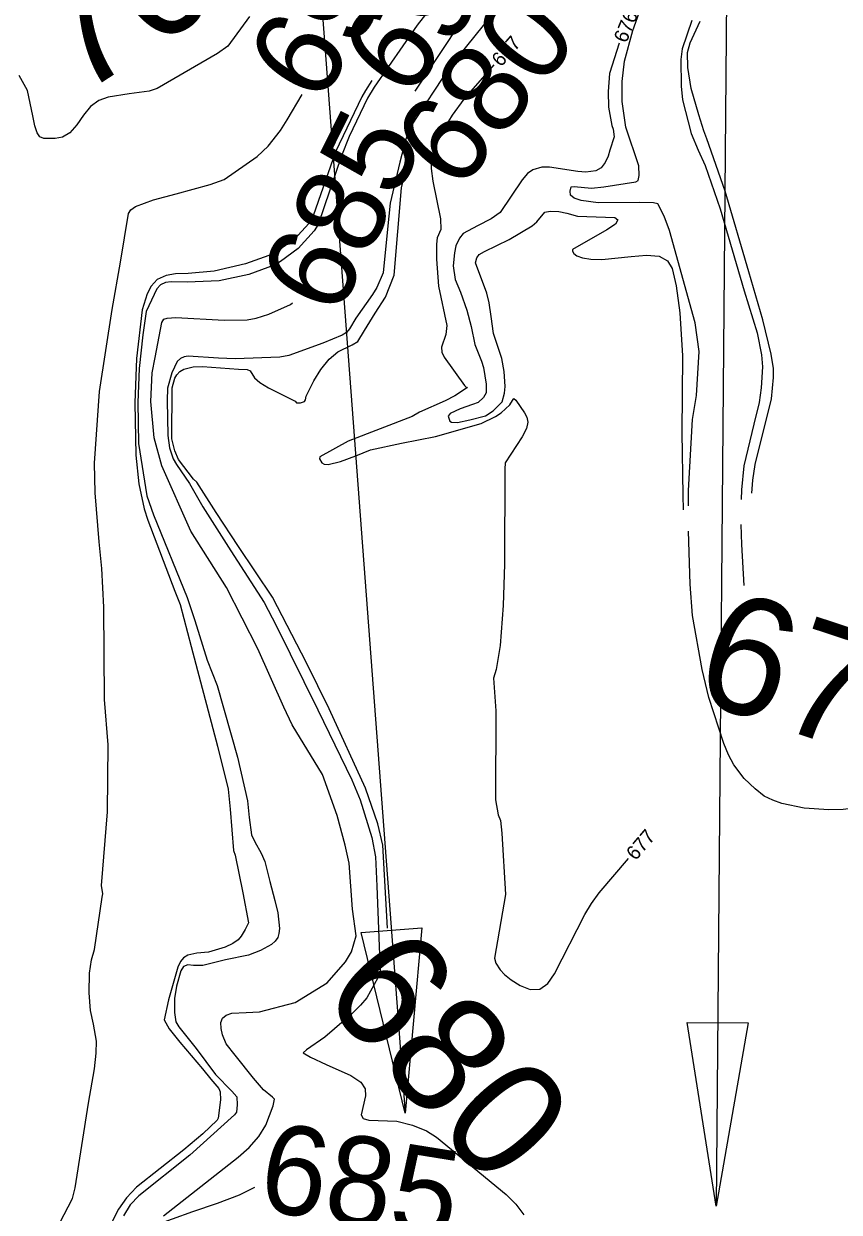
# Model space of a CAD drawing. Extents: x -291892836 to 2945206, y -477993085 to 1832792.
# Drawn here: x 1851264 to 1851493.5, y 544449.7 to 544783.9 of the extents above; entities that cross this region are included whole.
import ezdxf

# ---------------------------------------------------------------- set-up
doc = ezdxf.new("R2010")
doc.units = 0
for name, color, linetype in [('DT_X_Contour_Minor', 7, 'Continuous'), ('DT_X_Terrain_Ground_Line', 7, 'Continuous'), ('Level 19', 7, 'Continuous'), ('Level 40', 7, 'Continuous')]:
    doc.layers.add(name, color=color, linetype=linetype)

msp = doc.modelspace()

# ---------------------------------------------------------------- linework, layer by layer
at = {"layer": 'DT_X_Contour_Minor'}
for points in [[(1851388.6, 544801.3), (1851374.75, 544783.55), (1851362.59, 544766.11), (1851360.76, 544762.96), (1851355.57, 544752.19), (1851353.43, 544746.73), (1851346.86, 544727.5), (1851345.74, 544725.66), (1851341.27, 544720.75), (1851336.31, 544717.04)], [(1851402.99, 544796.19), (1851393.33, 544783.45), (1851383.94, 544771.77), (1851372.99, 544755.12), (1851371.54, 544751.49), (1851369.83, 544745.01), (1851367.12, 544733.48), (1851366.34, 544726.15), (1851365.2, 544713.86), (1851363.42, 544709.74), (1851362.19, 544707.78), (1851357.48, 544701.12), (1851355.66, 544698.13), (1851354.83, 544697.14), (1851353.64, 544696.34), (1851348.15, 544694.06), (1851338.66, 544690.65)], [(1851394.08, 544795.1), (1851374.06, 544764.99)], [(1851451.07, 544648.37), (1851451.11, 544652.67), (1851452.24, 544672.6), (1851453.38, 544679.39), (1851454.06, 544691.78), (1851452.97, 544699.83), (1851445.75, 544725.78), (1851444.28, 544729.78), (1851442.48, 544733.27), (1851441.25, 544733.58), (1851437.35, 544733.68), (1851425.67, 544733.57), (1851420.9, 544734.19), (1851418.96, 544734.83), (1851417.89, 544735.68), (1851417.77, 544736.82), (1851418.08, 544738.01), (1851418.9, 544738.14), (1851423.84, 544737.72), (1851427.24, 544738.06), (1851436.24, 544739.47), (1851436.97, 544739.88), (1851437.17, 544741.23), (1851437.12, 544743.97), (1851433.47, 544754.79), (1851432.4, 544762.06), (1851432.4, 544767.69), (1851433.13, 544773.41), (1851435.43, 544782.03), (1851437.64, 544788.29)], [(1851327.59, 544785.92), (1851321.44, 544777.58), (1851318.55, 544775.53), (1851301.57, 544765.7), (1851299.34, 544765), (1851293.65, 544764.18), (1851287.77, 544763.28), (1851285.17, 544762.32), (1851282.85, 544760.66), (1851280.82, 544758.2), (1851278.94, 544755.49), (1851277.02, 544753.26), (1851274.96, 544752.03), (1851272.9, 544751.61), (1851269.64, 544751.68), (1851268.56, 544752.11), (1851267.76, 544753.22), (1851267.15, 544755.2), (1851266.58, 544758)], [(1851452.02, 544784.79), (1851449.33, 544776.86), (1851448.91, 544773.86), (1851449, 544766.37), (1851449.42, 544762.48), (1851451.84, 544753.02), (1851453.8, 544748.35), (1851455.79, 544744.04), (1851460.03, 544731.91), (1851466.72, 544708.85), (1851470.43, 544696.98), (1851471.65, 544690.83), (1851471.89, 544687.41), (1851471.57, 544681.58), (1851470.94, 544677.43), (1851469.52, 544671.28), (1851466.7, 544659.62), (1851465.99, 544652.89), (1851465.91, 544650.13)], [(1851468.91, 544651.96), (1851469.16, 544655.53), (1851469.83, 544660.01), (1851474.43, 544678.47), (1851474.97, 544684.45), (1851475, 544687), (1851474.32, 544690.97), (1851472.02, 544700.66), (1851468.03, 544714.12), (1851461.39, 544736.84), (1851456.23, 544751.51), (1851455.44, 544753.76), (1851454.02, 544758.33), (1851451.83, 544765.72), (1851450.9, 544771.59), (1851450.83, 544775.83), (1851451.59, 544778.51), (1851454.36, 544784.64)], [(1851431.57, 544778.41), (1851428.9, 544769.95), (1851428.45, 544764.83), (1851428.56, 544760.48), (1851429.53, 544755.26), (1851429.86, 544754.26), (1851430.16, 544752.1), (1851428.95, 544748.36), (1851428.46, 544746.7), (1851427.65, 544744.88), (1851426.49, 544743.39), (1851425.01, 544742.56), (1851422.17, 544742.21), (1851419.96, 544742.38), (1851411.93, 544743.56), (1851409.84, 544743.55), (1851407.28, 544742.88), (1851405.75, 544741.84), (1851404.32, 544740.06), (1851398.08, 544730.85), (1851395.56, 544729.1), (1851391.75, 544727.09), (1851387.65, 544724.89), (1851386.68, 544723.58), (1851385.61, 544721.47), (1851385.22, 544719.53), (1851384.88, 544715.87), (1851385.45, 544712.02), (1851386.89, 544708.47), (1851388.67, 544703.35), (1851389.9, 544698.79), (1851390.94, 544693.68), (1851392.8, 544689), (1851393.42, 544687.28), (1851394.16, 544682.6), (1851394.12, 544680.11), (1851393.42, 544678.82), (1851391.86, 544677.42), (1851390.3, 544676.88), (1851386.87, 544675.65), (1851383.99, 544674.35), (1851383.46, 544673.53), (1851383.94, 544672.17), (1851384.42, 544671.86), (1851386.09, 544671.81), (1851389.55, 544672.54), (1851393.93, 544673.69), (1851396.11, 544675.05), (1851398.7, 544677.63), (1851399.31, 544680.02), (1851399.46, 544681.9), (1851399.23, 544686.17), (1851398.56, 544689.79), (1851396.2, 544696.78), (1851395.56, 544701.61), (1851395, 544705.42), (1851394.32, 544708.12), (1851391.12, 544716.65), (1851391.5, 544718.11), (1851392.15, 544718.99), (1851393.65, 544719.86), (1851400.64, 544723.25), (1851407.07, 544727.13), (1851408.43, 544728.2), (1851410.69, 544730.95), (1851412.12, 544731.25), (1851414.63, 544731.1), (1851416.9, 544730.63), (1851419.84, 544729.76), (1851430.35, 544729.47), (1851431.21, 544728.77), (1851430.56, 544727.6), (1851428.15, 544725.94), (1851418.42, 544720.42), (1851418.43, 544719.97), (1851418.81, 544719.34), (1851419.69, 544718.65), (1851421.25, 544718.06), (1851423.61, 544717.7), (1851426.73, 544717.65), (1851434.95, 544718.48), (1851439.28, 544718.88), (1851442.86, 544718.58), (1851445.19, 544717.22), (1851446.49, 544715.09), (1851447.63, 544710.24), (1851448.61, 544702.67), (1851449.36, 544690.54), (1851449.23, 544669.02), (1851449.51, 544651.38), (1851449.62, 544647.19)], [(1851396.33, 544772.33), (1851387.85, 544762.67), (1851384.55, 544758.16), (1851381.51, 544753.18), (1851380.08, 544750.38), (1851378.69, 544744.39), (1851378.65, 544743.25), (1851379.18, 544739.65), (1851381.32, 544729.1), (1851381.38, 544726.07), (1851380.37, 544723.75), (1851380.14, 544721.92), (1851380.19, 544717.76), (1851380.73, 544710.09), (1851383.07, 544699.1), (1851382.76, 544696.52), (1851381.63, 544692.93), (1851381.71, 544691.54), (1851382.35, 544690.15), (1851388.09, 544682.2), (1851388.54, 544681.76), (1851388.88, 544681.6), (1851385.36, 544679.31), (1851382.64, 544677.9), (1851375.43, 544674.65), (1851373.33, 544673.43), (1851355.35, 544666.55), (1851347.3, 544662.14), (1851347.24, 544661.59), (1851347.87, 544660.43), (1851348.61, 544660.03), (1851349.72, 544660), (1851353.13, 544660.83), (1851357.5, 544662.46), (1851361.63, 544664.06), (1851370.32, 544666), (1851379.87, 544667.87), (1851392.72, 544671.46), (1851396.8, 544673.44), (1851398.35, 544674.46), (1851400.82, 544676.71), (1851401.6, 544677.94), (1851401.92, 544678.58), (1851402.46, 544678.08), (1851404.91, 544674.47), (1851405.57, 544673.27), (1851405.89, 544671.86), (1851405.54, 544670.06), (1851404.33, 544667.8), (1851399.5, 544660.49), (1851399.38, 544658.64), (1851399.28, 544632), (1851398.93, 544620.31), (1851398.07, 544609.07), (1851396.95, 544602.38), (1851396.26, 544599.92), (1851396.89, 544590.68), (1851396.81, 544565.7), (1851397.56, 544561.43), (1851398.17, 544559.87), (1851398.52, 544556.33), (1851399.61, 544539.08), (1851396.47, 544521.18), (1851396.85, 544519.79), (1851398.05, 544517.93), (1851399.3, 544516.58), (1851401.16, 544515.03), (1851403.7, 544513.46), (1851406.56, 544512.39), (1851409.28, 544512.43), (1851411.53, 544514), (1851413.38, 544516.72), (1851421.91, 544533.41), (1851423.83, 544536.57), (1851425.92, 544539.51), (1851434.21, 544549.16)], [(1851266.58, 544758), (1851265.11, 544765.12), (1851262.7, 544769.39)], [(1851362.02, 544767.93), (1851360.21, 544765.16), (1851359.2, 544763.39), (1851351.76, 544747.87), (1851345.5, 544729.93), (1851344.37, 544727.82), (1851340.09, 544723.25), (1851334.34, 544719.2), (1851326.45, 544716.38), (1851317.65, 544714.34), (1851310.29, 544713.73), (1851306.76, 544713.58), (1851304.08, 544713.13), (1851301.61, 544712.02), (1851299.85, 544710.13), (1851298.76, 544707.92), (1851297.35, 544703.45), (1851295.79, 544689.74), (1851295.25, 544677.35), (1851295.52, 544662.63), (1851296.39, 544654.57), (1851297.92, 544647.48), (1851298.95, 544644.36), (1851306.58, 544624.4), (1851308.01, 544620.58), (1851311.15, 544608.83), (1851318.59, 544580.77), (1851321.57, 544568.66), (1851322.1, 544563.04), (1851323.08, 544551.45), (1851323.53, 544550.12), (1851325.71, 544539.52), (1851327.25, 544531.12), (1851326.29, 544529.21), (1851325.21, 544527.32), (1851324.36, 544526.29), (1851322.9, 544525.27), (1851320.71, 544524.29), (1851316.05, 544522.9), (1851312.74, 544522.57), (1851310.21, 544521.99), (1851309, 544521.3), (1851308.1, 544520.25), (1851307.37, 544518.62), (1851304.77, 544509.46), (1851303.53, 544503.86), (1851304.91, 544501.34), (1851307.97, 544497.51), (1851314.32, 544490.07), (1851316.66, 544487.15), (1851318.94, 544484.48), (1851319.32, 544483.56), (1851319.37, 544481.31), (1851318.77, 544476.14), (1851318.47, 544475.62), (1851314.41, 544471.76), (1851309.06, 544467.31), (1851295.73, 544456.76), (1851292.9, 544453.75), (1851290.66, 544450.57), (1851288.44, 544446.23)], [(1851274.17, 544446.71), (1851277.72, 544453.59), (1851278.45, 544456.58), (1851282.27, 544480.36), (1851283.95, 544490.04), (1851284.44, 544494.43), (1851284.45, 544497.85), (1851283.64, 544502.58), (1851282.81, 544506.47), (1851282.41, 544511.44), (1851282.55, 544516.96), (1851283.13, 544520.67), (1851283.94, 544523.63), (1851286.05, 544538.32), (1851286.31, 544539.26), (1851285.91, 544541.56), (1851287.57, 544562.36), (1851287.73, 544581.12), (1851286.79, 544593.86), (1851286.57, 544619.82), (1851286.03, 544630.7), (1851285.23, 544638.21), (1851284.14, 544651.97), (1851283.89, 544660.32), (1851285.32, 544680.46), (1851288.9, 544703.59), (1851291.27, 544716.85), (1851293.54, 544730.56), (1851294.16, 544731.61), (1851295.51, 544732.51), (1851300.5, 544734.37), (1851306.94, 544736.06), (1851316.51, 544738.75), (1851320.4, 544740.15), (1851329.67, 544746.56), (1851332.79, 544749.48), (1851336.31, 544753.86), (1851338.17, 544756.85), (1851342.41, 544764.01)], [(1851366.38, 544529.63), (1851365.04, 544552.91), (1851363.68, 544558.94), (1851360.18, 544568.99), (1851349.94, 544591.3), (1851343.59, 544604.19), (1851334.04, 544622.7), (1851324.48, 544636.9), (1851318.17, 544646.45), (1851312.69, 544655.01), (1851311.75, 544655.82), (1851307.61, 544661.4), (1851306.5, 544663.79), (1851305.71, 544667.17), (1851305.77, 544681.53), (1851306.56, 544684.21), (1851307.08, 544685.23), (1851307.9, 544686.11), (1851309.06, 544686.77), (1851311.71, 544687.45), (1851314.35, 544687.52), (1851324.43, 544686.82), (1851326.94, 544686.7), (1851327.75, 544686.28), (1851328.99, 544684.35), (1851330.43, 544683), (1851332.94, 544681.53), (1851340.39, 544677.83), (1851340.74, 544677.34), (1851341.89, 544677.35), (1851343.01, 544677.68), (1851343.29, 544678.12), (1851343.53, 544679.22), (1851345.68, 544683.55), (1851347.65, 544686.72), (1851349.97, 544689.61), (1851352.41, 544691.66), (1851356.41, 544693.66), (1851358.03, 544694.55), (1851359.88, 544697.61), (1851362.92, 544702.56), (1851365.85, 544707.01), (1851368.22, 544713.17), (1851370.36, 544737.8), (1851372.1, 544744.98)], [(1851336.31, 544717.04), (1851334.46, 544716.04), (1851327.39, 544713.39), (1851319.03, 544711.65), (1851310.03, 544711.26), (1851305.51, 544711.36), (1851303.9, 544711.11), (1851302.49, 544710.49), (1851301.49, 544709.4), (1851298.44, 544703.04), (1851297.56, 544696.43), (1851296.54, 544687), (1851296.16, 544677.43), (1851296.35, 544665.86), (1851298.67, 544651.16), (1851300.52, 544645.85), (1851309.99, 544622.59), (1851312.17, 544616.11), (1851315.62, 544604.92), (1851318.48, 544597.79), (1851324.16, 544577.69), (1851326.97, 544565.45), (1851327.43, 544560.75), (1851328.08, 544555.89), (1851329.08, 544553.88), (1851330.87, 544550.67), (1851331.82, 544548.36), (1851333.29, 544542.77), (1851334.71, 544537.38), (1851335.57, 544533.95), (1851335.97, 544529.52), (1851335.84, 544528.13), (1851335.49, 544526.96), (1851334.82, 544525.95), (1851333.74, 544525.03), (1851330.6, 544523.33), (1851327.27, 544522.05), (1851320.82, 544520.73), (1851314.43, 544519.13), (1851311.83, 544519.13), (1851310.19, 544519.26), (1851308.94, 544518.8), (1851308.21, 544517.59), (1851307.03, 544513.25), (1851306.47, 544509.86), (1851306.42, 544505.89), (1851306.86, 544503.22), (1851307.71, 544501.84), (1851312.53, 544495.77), (1851318.01, 544488.43), (1851322.58, 544483.75), (1851323.99, 544482.18), (1851324.1, 544479.91), (1851323.86, 544477.85), (1851323.31, 544477.11), (1851310.75, 544465.78), (1851296.36, 544454.37), (1851293.98, 544451.79), (1851292.05, 544448.71)], [(1851303.32, 544448.67), (1851324.34, 544465.2), (1851327.41, 544467.9), (1851330.18, 544470.98), (1851332.18, 544474.24), (1851334.17, 544479.61), (1851334.59, 544481.53), (1851333.98, 544482.09), (1851331.51, 544484.11), (1851328.68, 544487.4), (1851323.5, 544493.87), (1851321.01, 544497.06), (1851319.99, 544499.58), (1851319.57, 544501.37), (1851319.49, 544503.06), (1851319.96, 544504.33), (1851320.99, 544505.18), (1851322.55, 544505.67), (1851326.64, 544505.93), (1851330.34, 544506.04), (1851340.42, 544508.72), (1851349.37, 544514.21), (1851354.61, 544520.12), (1851356.24, 544522.93), (1851357.56, 544527.44), (1851356.54, 544534.99), (1851355.62, 544547.87), (1851354.48, 544552.94), (1851352.18, 544561.32), (1851348.11, 544572.81), (1851339.56, 544586.78), (1851337.25, 544591.78), (1851329.93, 544608.12), (1851321.08, 544625.41), (1851311.01, 544641.26), (1851302.91, 544659.65), (1851300.73, 544667.43), (1851299.82, 544677.73), (1851300.18, 544685.73), (1851300.98, 544690.11), (1851302.89, 544699.92), (1851303.4, 544700.82), (1851304.38, 544701.14), (1851306.8, 544701.32), (1851320.45, 544700.55), (1851326.9, 544700.67), (1851329.47, 544701.14), (1851332.96, 544702.24), (1851339.12, 544704.98), (1851339.67, 544705.41)], [(1851338.66, 544690.65), (1851336.11, 544690.2), (1851323.5, 544689.73), (1851318.86, 544689.87), (1851310.3, 544690.41), (1851309.13, 544690.24), (1851308.1, 544689.8), (1851307.18, 544688.9), (1851305.7, 544685.78), (1851304.51, 544681.42), (1851304.38, 544677.97), (1851304.55, 544668.17), (1851305.05, 544664.67), (1851306.03, 544661.61), (1851307.03, 544659.99), (1851310.7, 544654.64), (1851314.46, 544648.09), (1851322.31, 544635.66), (1851331.68, 544621.21), (1851335.08, 544614.74), (1851346.79, 544591.04), (1851356.37, 544571.35), (1851358.66, 544565.7), (1851362, 544555.12), (1851362.99, 544549.66), (1851363.39, 544541.44), (1851364.35, 544517.34), (1851363.65, 544515.63), (1851360.6, 544510.02), (1851358.83, 544507.92), (1851356.28, 544505.4), (1851348.76, 544498.92), (1851343.59, 544495.41), (1851342.69, 544494.57), (1851344.75, 544493.33), (1851349.09, 544491.26), (1851356.1, 544488.14), (1851358.84, 544486.32), (1851360.08, 544484.41), (1851360.15, 544482.48), (1851358.94, 544477.16), (1851359.53, 544476.09), (1851361.11, 544475.64), (1851368.98, 544475.29), (1851373.42, 544474.2), (1851377.35, 544472.6), (1851380.14, 544470.81), (1851399.82, 544454.74), (1851402.5, 544451.96), (1851404.75, 544448.95)], [(1851531.68, 544579.29), (1851529.6, 544578.6), (1851523.46, 544575.49), (1851517, 544571.2), (1851510.54, 544567.23), (1851508.07, 544565.62), (1851504.12, 544564.17), (1851494.6, 544562.93), (1851490.63, 544562.85), (1851483.62, 544563.35), (1851477.39, 544564.65), (1851474.87, 544565.59), (1851472.41, 544566.76), (1851469.85, 544568.81), (1851466.75, 544571.69), (1851463.85, 544575.55), (1851462.39, 544578.37), (1851461, 544581.54), (1851456.81, 544594.48), (1851454.94, 544602.3), (1851452.23, 544617.54), (1851451.53, 544626.35), (1851451.1, 544641.26)], [(1851465.85, 544643.07), (1851466.02, 544637.52), (1851466.71, 544625.91)], [(1851328.98, 544456.67), (1851324.63, 544454.49), (1851318.47, 544452.23), (1851311.49, 544449.86), (1851300.11, 544445.73)]]:
    msp.add_lwpolyline(points, dxfattribs=at)
at = {"layer": 'Level 40'}
for p, q in [((1851304.99, 545356.29), (1851371.4, 544477.62)), ((1851466.42, 545337.49), (1851458.89, 544451.45)), ((1851358.96, 544528.4), (1851376.09, 544529.7)), ((1851371.4, 544477.62), (1851358.96, 544528.4)), ((1851376.09, 544529.7), (1851371.4, 544477.62)), ((1851458.89, 544451.45), (1851450.75, 544503.1)), ((1851450.75, 544503.1), (1851467.92, 544502.95)), ((1851467.92, 544502.95), (1851458.89, 544451.45))]:
    msp.add_line(p, q, dxfattribs=at)

# ---------------------------------------------------------------- texts
at = {"layer": 'DT_X_Terrain_Ground_Line'}
for s, height, rotation, p in [('700', 33, 33.0081, (1851279.42, 544763.12)), ('695', 25, 57.8859, (1851346.89, 544760.55)), ('690', 25, 52.6606, (1851371.69, 544762)), ('680', 25, 51.8584, (1851386.36, 544736.06)), ('685', 25, 63.7133, (1851352.14, 544700.79)), ('675', 33, 341.7808, (1851451.35, 544594.26)), ('680', 33, 311.7012, (1851346.89, 544510.7)), ('685', 25, 350.8575, (1851329.31, 544450.6))]:
    msp.add_text(s, height=height, rotation=rotation, dxfattribs=at).set_placement(p)
at = {"layer": 'Level 19'}
for s, rotation, p in [('676', 67.7064, (1851433.59, 544778.28)), ('677', 48.7243, (1851398.32, 544771.56)), ('677', 49.3259, (1851436.21, 544548.41))]:
    msp.add_text(s, height=4, rotation=rotation, dxfattribs=at).set_placement(p)

doc.saveas('drawing.dxf')
